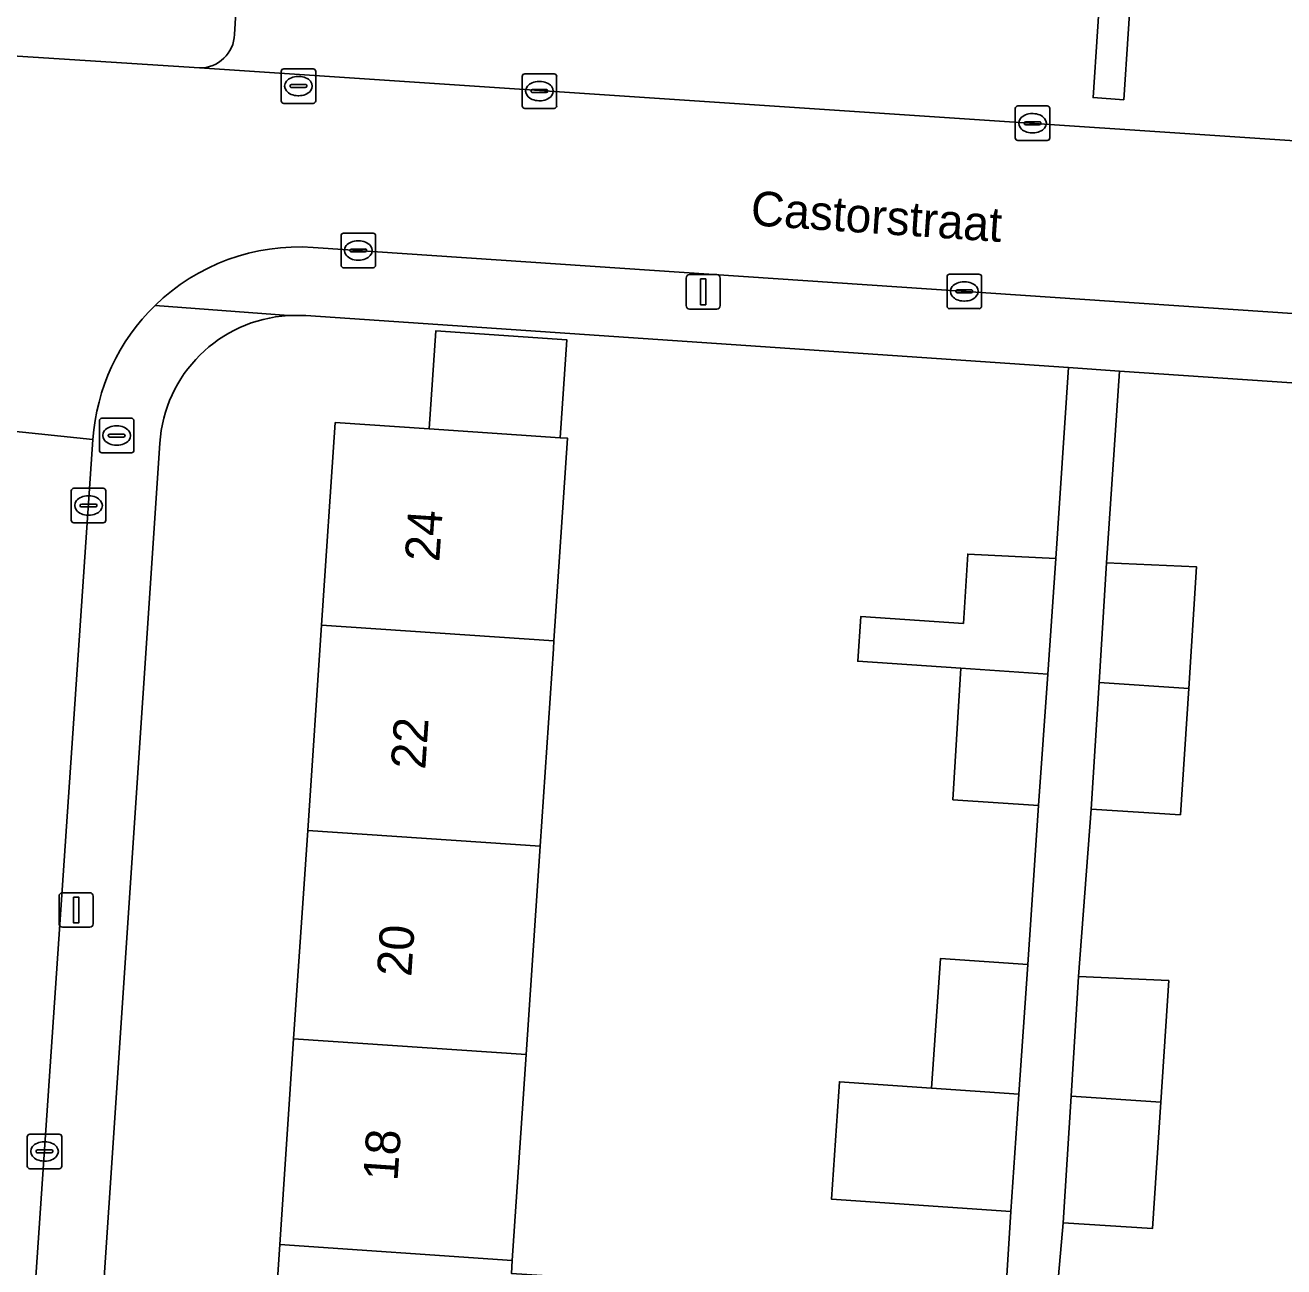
# Model space of a CAD drawing. Extents: x 161848 to 162726, y 385382 to 386521.
# Drawn here: x 161942.63 to 161979.1, y 385678.71 to 385714.68 of the extents above; entities that cross this region are included whole.
import ezdxf

# ---------------------------------------------------------------- set-up
doc = ezdxf.new("R2010")
doc.units = 0
for name, color, linetype in [('IMGEO_Brandkraan', 7, 'Continuous'), ('IMGEO_Erf', 7, 'Continuous'), ('IMGEO_Kolk', 7, 'Continuous'), ('IMGEO_Lichtmast', 7, 'Continuous'), ('IMGEO_Openbare_ruimte_label', 7, 'Continuous'), ('IMGEO_Pand', 7, 'Continuous'), ('IMGEO_Pand_nummerreeks', 7, 'Continuous'), ('IMGEO_Parkeervlak_open', 7, 'Continuous'), ('IMGEO_Rijbaan_lokaal_open', 7, 'Continuous'), ('IMGEO_Rioolput', 7, 'Continuous'), ('IMGEO_Voetpad_open', 7, 'Continuous')]:
    doc.layers.add(name, color=color, linetype=linetype)

msp = doc.modelspace()

# ---------------------------------------------------------------- linework, layer by layer
at = {"layer": 'IMGEO_Brandkraan'}
for p, q in [((161944.851, 385703.289), (161945.703, 385703.289)), ((161944.776, 385702.363), (161944.776, 385703.215)), ((161945.264, 385703.069), (161945.289, 385703.069)), ((161945.777, 385703.215), (161945.777, 385702.363)), ((161945.035, 385702.783), (161945.035, 385702.795)), ((161945.473, 385702.746), (161945.075, 385702.746)), ((161945.078, 385702.832), (161945.476, 385702.832)), ((161945.287, 385702.509), (161945.262, 385702.509)), ((161945.519, 385702.795), (161945.519, 385702.783)), ((161945.703, 385702.289), (161944.851, 385702.289))]:
    msp.add_line(p, q, dxfattribs=at)
for points in [[(161944.851, 385703.289), (161945.703, 385703.289)], [(161944.776, 385702.363), (161944.776, 385703.215)], [(161945.777, 385703.215), (161945.777, 385702.363)], [(161945.703, 385702.289), (161944.851, 385702.289)]]:
    msp.add_lwpolyline(points, dxfattribs=at)
for centre, radius, start, end in [((161944.853, 385703.213), 0.0765, 91.552, 178.448), ((161944.853, 385703.213), 0.0765, 91.552, 178.448), ((161945.701, 385703.213), 0.0765, 1.552, 88.448), ((161945.701, 385703.213), 0.0765, 1.552, 88.448), ((161945.075, 385702.792), 0.0403, 85.8775, 175.7526), ((161945.072, 385702.782), 0.0366, 178.938, 274.7102), ((161945.476, 385702.789), 0.043, 264.8664, 352.4533), ((161945.48, 385702.794), 0.0386, 1.7309, 96.639), ((161944.853, 385702.365), 0.0765, 181.552, 268.448), ((161944.853, 385702.365), 0.0765, 181.552, 268.448), ((161945.701, 385702.365), 0.0765, 271.552, 358.448), ((161945.701, 385702.365), 0.0765, 271.552, 358.448)]:
    msp.add_arc(centre, radius, start, end, dxfattribs=at)
for centre, major_axis, ratio, start_param, end_param in [((161945.263, 385702.789), (-0.387, 0.002), 0.722429, 4.712389, 7.853982), ((161945.288, 385702.789), (-0.39, 0.002), 0.717154, 1.570796, 4.712389)]:
    msp.add_ellipse(centre, major_axis=major_axis, ratio=ratio, start_param=start_param, end_param=end_param, dxfattribs=at)
at = {"layer": 'IMGEO_Erf'}
for points in [[(161970.385, 385668.193), (161967.899, 385668.362), (161968.129, 385672.173), (161968.329, 385675.481), (161970.879, 385675.348), (161971.188, 385680.308), (161965.988, 385680.667), (161966.222, 385684.067), (161968.889, 385683.883), (161969.148, 385687.638), (161971.682, 385687.463), (161971.995, 385692.068), (161969.509, 385692.237), (161969.739, 385696.048), (161966.755, 385696.251), (161966.843, 385697.548), (161969.817, 385697.346), (161969.939, 385699.356), (161972.489, 385699.223), (161972.865, 385704.758), (161950.757, 385706.262)], [(161949.605, 385673.424), (161950.004, 385679.348), (161950.406, 385685.311), (161950.813, 385691.345), (161951.215, 385697.299), (161951.61, 385703.166), (161954.33, 385702.982), (161954.523, 385705.821), (161958.321, 385705.564), (161958.128, 385702.725), (161958.345, 385702.71), (161957.95, 385696.844), (161957.934, 385696.609), (161957.548, 385690.89), (161957.142, 385684.856), (161956.74, 385678.892), (161956.715, 385678.515)], [(162001.131, 385702.827), (161999.588, 385702.941), (161974.338, 385704.658), (161973.96, 385699.104), (161976.574, 385698.983), (161976.344, 385695.463), (161976.105, 385691.802), (161973.517, 385691.96), (161973.151, 385687.121), (161975.765, 385687), (161975.535, 385683.48), (161975.296, 385679.819), (161972.708, 385679.977), (161972.485, 385677.457)], [(161946.526, 385702.567), (161941.6, 385628.889)]]:
    msp.add_lwpolyline(points, dxfattribs=at)
for centre, radius, start, end in [((161950.488, 385702.3), 3.971, 93.3925, 176.1445), ((161950.489, 385702.298), 3.973, 86.1361, 93.4092)]:
    msp.add_arc(centre, radius, start, end, dxfattribs=at)
at = {"layer": 'IMGEO_Kolk'}
for p, q in [((161957.027, 385712.342), (161957.027, 385713.194)), ((161957.102, 385713.268), (161957.954, 385713.268)), ((161958.028, 385713.194), (161958.028, 385712.342)), ((161957.286, 385712.762), (161957.286, 385712.774)), ((161957.724, 385712.725), (161957.326, 385712.725)), ((161957.329, 385712.811), (161957.727, 385712.811)), ((161957.515, 385713.048), (161957.54, 385713.048)), ((161957.77, 385712.774), (161957.77, 385712.762)), ((161957.538, 385712.488), (161957.513, 385712.488)), ((161957.954, 385712.268), (161957.102, 385712.268)), ((161971.319, 385711.411), (161971.319, 385712.263)), ((161971.394, 385712.337), (161972.246, 385712.337)), ((161971.807, 385712.117), (161971.832, 385712.117)), ((161972.32, 385712.263), (161972.32, 385711.411)), ((161971.578, 385711.831), (161971.578, 385711.843)), ((161972.016, 385711.794), (161971.618, 385711.794)), ((161971.621, 385711.88), (161972.019, 385711.88)), ((161972.062, 385711.843), (161972.062, 385711.831)), ((161972.246, 385711.337), (161971.394, 385711.337)), ((161971.83, 385711.557), (161971.805, 385711.557)), ((161951.779, 385707.724), (161951.779, 385708.576)), ((161951.854, 385708.65), (161952.706, 385708.65)), ((161952.267, 385708.43), (161952.292, 385708.43)), ((161952.78, 385708.576), (161952.78, 385707.724)), ((161952.038, 385708.144), (161952.038, 385708.156)), ((161952.476, 385708.107), (161952.078, 385708.107)), ((161952.081, 385708.193), (161952.479, 385708.193)), ((161952.522, 385708.156), (161952.522, 385708.144)), ((161952.706, 385707.65), (161951.854, 385707.65)), ((161952.29, 385707.87), (161952.265, 385707.87)), ((161969.34, 385706.539), (161969.34, 385707.391)), ((161969.415, 385707.465), (161970.267, 385707.465)), ((161970.341, 385707.391), (161970.341, 385706.539)), ((161969.599, 385706.959), (161969.599, 385706.971)), ((161970.037, 385706.922), (161969.639, 385706.922)), ((161969.642, 385707.008), (161970.04, 385707.008)), ((161969.828, 385707.245), (161969.853, 385707.245)), ((161970.083, 385706.971), (161970.083, 385706.959)), ((161969.851, 385706.685), (161969.826, 385706.685)), ((161970.267, 385706.465), (161969.415, 385706.465)), ((161943.961, 385700.336), (161943.961, 385701.188)), ((161944.036, 385701.262), (161944.888, 385701.262)), ((161944.962, 385701.188), (161944.962, 385700.336)), ((161944.22, 385700.756), (161944.22, 385700.768)), ((161944.658, 385700.719), (161944.26, 385700.719)), ((161944.263, 385700.805), (161944.661, 385700.805)), ((161944.449, 385701.042), (161944.474, 385701.042)), ((161944.704, 385700.768), (161944.704, 385700.756)), ((161944.472, 385700.482), (161944.447, 385700.482)), ((161944.888, 385700.262), (161944.036, 385700.262)), ((161942.685, 385681.623), (161942.685, 385682.475)), ((161942.76, 385682.549), (161943.612, 385682.549)), ((161943.686, 385682.475), (161943.686, 385681.623)), ((161942.987, 385682.092), (161943.385, 385682.092)), ((161943.173, 385682.329), (161943.198, 385682.329)), ((161942.944, 385682.043), (161942.944, 385682.055)), ((161943.382, 385682.006), (161942.984, 385682.006)), ((161943.196, 385681.769), (161943.171, 385681.769)), ((161943.428, 385682.055), (161943.428, 385682.043)), ((161943.612, 385681.549), (161942.76, 385681.549))]:
    msp.add_line(p, q, dxfattribs=at)
for points in [[(161957.027, 385712.342), (161957.027, 385713.194)], [(161957.102, 385713.268), (161957.954, 385713.268)], [(161958.028, 385713.194), (161958.028, 385712.342)], [(161957.954, 385712.268), (161957.102, 385712.268)], [(161971.319, 385711.411), (161971.319, 385712.263)], [(161971.394, 385712.337), (161972.246, 385712.337)], [(161972.32, 385712.263), (161972.32, 385711.411)], [(161972.246, 385711.337), (161971.394, 385711.337)], [(161951.779, 385707.724), (161951.779, 385708.576)], [(161951.854, 385708.65), (161952.706, 385708.65)], [(161952.78, 385708.576), (161952.78, 385707.724)], [(161952.706, 385707.65), (161951.854, 385707.65)], [(161969.34, 385706.539), (161969.34, 385707.391)], [(161969.415, 385707.465), (161970.267, 385707.465)], [(161970.341, 385707.391), (161970.341, 385706.539)], [(161970.267, 385706.465), (161969.415, 385706.465)], [(161943.961, 385700.336), (161943.961, 385701.188)], [(161944.036, 385701.262), (161944.888, 385701.262)], [(161944.962, 385701.188), (161944.962, 385700.336)], [(161944.888, 385700.262), (161944.036, 385700.262)], [(161942.685, 385681.623), (161942.685, 385682.475)], [(161942.76, 385682.549), (161943.612, 385682.549)], [(161943.686, 385682.475), (161943.686, 385681.623)], [(161943.612, 385681.549), (161942.76, 385681.549)]]:
    msp.add_lwpolyline(points, dxfattribs=at)
for centre, radius, start, end in [((161957.104, 385713.192), 0.0765, 91.552, 178.448), ((161957.104, 385713.192), 0.0765, 91.552, 178.448), ((161957.952, 385713.192), 0.0765, 1.552, 88.448), ((161957.952, 385713.192), 0.0765, 1.552, 88.448), ((161957.326, 385712.771), 0.0403, 85.8775, 175.7526), ((161957.323, 385712.761), 0.0366, 178.938, 274.7102), ((161957.727, 385712.768), 0.043, 264.8664, 352.4533), ((161957.731, 385712.773), 0.0386, 1.7309, 96.639), ((161957.104, 385712.344), 0.0765, 181.552, 268.448), ((161957.104, 385712.344), 0.0765, 181.552, 268.448), ((161957.952, 385712.344), 0.0765, 271.552, 358.448), ((161957.952, 385712.344), 0.0765, 271.552, 358.448), ((161971.396, 385712.261), 0.0765, 91.552, 178.448), ((161971.396, 385712.261), 0.0765, 91.552, 178.448), ((161972.244, 385712.261), 0.0765, 1.552, 88.448), ((161972.244, 385712.261), 0.0765, 1.552, 88.448), ((161971.618, 385711.84), 0.0403, 85.8775, 175.7526), ((161971.615, 385711.83), 0.0366, 178.938, 274.7102), ((161972.019, 385711.837), 0.043, 264.8664, 352.4533), ((161972.023, 385711.842), 0.0386, 1.7309, 96.639), ((161971.396, 385711.413), 0.0765, 181.552, 268.448), ((161971.396, 385711.413), 0.0765, 181.552, 268.448), ((161972.244, 385711.413), 0.0765, 271.552, 358.448), ((161972.244, 385711.413), 0.0765, 271.552, 358.448), ((161951.856, 385708.574), 0.0765, 91.552, 178.448), ((161951.856, 385708.574), 0.0765, 91.552, 178.448), ((161952.704, 385708.574), 0.0765, 1.552, 88.448), ((161952.704, 385708.574), 0.0765, 1.552, 88.448), ((161952.078, 385708.153), 0.0403, 85.8775, 175.7526), ((161952.075, 385708.143), 0.0366, 178.938, 274.7102), ((161952.479, 385708.15), 0.043, 264.8664, 352.4533), ((161952.483, 385708.155), 0.0386, 1.7309, 96.639), ((161951.856, 385707.726), 0.0765, 181.552, 268.448), ((161951.856, 385707.726), 0.0765, 181.552, 268.448), ((161952.704, 385707.726), 0.0765, 271.552, 358.448), ((161952.704, 385707.726), 0.0765, 271.552, 358.448), ((161969.417, 385707.389), 0.0765, 91.552, 178.448), ((161969.417, 385707.389), 0.0765, 91.552, 178.448), ((161970.265, 385707.389), 0.0765, 1.552, 88.448), ((161970.265, 385707.389), 0.0765, 1.552, 88.448), ((161969.639, 385706.968), 0.0403, 85.8775, 175.7526), ((161969.636, 385706.958), 0.0366, 178.938, 274.7102), ((161970.04, 385706.965), 0.043, 264.8664, 352.4533), ((161970.044, 385706.97), 0.0386, 1.7309, 96.639), ((161969.417, 385706.541), 0.0765, 181.552, 268.448), ((161969.417, 385706.541), 0.0765, 181.552, 268.448), ((161970.265, 385706.541), 0.0765, 271.552, 358.448), ((161970.265, 385706.541), 0.0765, 271.552, 358.448), ((161944.038, 385701.186), 0.0765, 91.552, 178.448), ((161944.038, 385701.186), 0.0765, 91.552, 178.448), ((161944.886, 385701.186), 0.0765, 1.552, 88.448), ((161944.886, 385701.186), 0.0765, 1.552, 88.448), ((161944.26, 385700.765), 0.0403, 85.8775, 175.7526), ((161944.257, 385700.755), 0.0366, 178.938, 274.7102), ((161944.661, 385700.762), 0.043, 264.8664, 352.4533), ((161944.665, 385700.767), 0.0386, 1.7309, 96.639), ((161944.038, 385700.338), 0.0765, 181.552, 268.448), ((161944.038, 385700.338), 0.0765, 181.552, 268.448), ((161944.886, 385700.338), 0.0765, 271.552, 358.448), ((161944.886, 385700.338), 0.0765, 271.552, 358.448), ((161942.762, 385682.473), 0.0765, 91.552, 178.448), ((161942.762, 385682.473), 0.0765, 91.552, 178.448), ((161943.61, 385682.473), 0.0765, 1.552, 88.448), ((161943.61, 385682.473), 0.0765, 1.552, 88.448), ((161942.984, 385682.052), 0.0403, 85.8775, 175.7526), ((161943.389, 385682.054), 0.0386, 1.7309, 96.639), ((161942.981, 385682.042), 0.0366, 178.938, 274.7102), ((161943.385, 385682.049), 0.043, 264.8664, 352.4533), ((161942.762, 385681.625), 0.0765, 181.552, 268.448), ((161942.762, 385681.625), 0.0765, 181.552, 268.448), ((161943.61, 385681.625), 0.0765, 271.552, 358.448), ((161943.61, 385681.625), 0.0765, 271.552, 358.448)]:
    msp.add_arc(centre, radius, start, end, dxfattribs=at)
for centre, major_axis, ratio, start_param, end_param in [((161957.514, 385712.768), (-0.387, 0.002), 0.722429, 4.712389, 7.853982), ((161957.539, 385712.768), (-0.39, 0.002), 0.717154, 1.570796, 4.712389), ((161971.806, 385711.837), (-0.387, 0.002), 0.722429, 4.712389, 7.853982), ((161971.831, 385711.837), (-0.39, 0.002), 0.717154, 1.570796, 4.712389), ((161952.266, 385708.15), (-0.387, 0.002), 0.722429, 4.712389, 7.853982), ((161952.291, 385708.15), (-0.39, 0.002), 0.717154, 1.570796, 4.712389), ((161969.827, 385706.965), (-0.387, 0.002), 0.722429, 4.712389, 7.853982), ((161969.852, 385706.965), (-0.39, 0.002), 0.717154, 1.570796, 4.712389), ((161944.448, 385700.762), (-0.387, 0.002), 0.722429, 4.712389, 7.853982), ((161944.473, 385700.762), (-0.39, 0.002), 0.717154, 1.570796, 4.712389), ((161943.172, 385682.049), (-0.387, 0.002), 0.722429, 4.712389, 7.853982), ((161943.197, 385682.049), (-0.39, 0.002), 0.717154, 1.570796, 4.712389)]:
    msp.add_ellipse(centre, major_axis=major_axis, ratio=ratio, start_param=start_param, end_param=end_param, dxfattribs=at)
at = {"layer": 'IMGEO_Lichtmast'}
for p, q in [((161961.778, 385706.552), (161961.778, 385707.352)), ((161961.778, 385707.352), (161961.778, 385706.552)), ((161961.878, 385707.452), (161962.668, 385707.452)), ((161962.668, 385707.452), (161961.878, 385707.452)), ((161962.768, 385707.352), (161962.768, 385706.552)), ((161962.768, 385706.552), (161962.768, 385707.352)), ((161962.668, 385706.452), (161961.878, 385706.452)), ((161961.878, 385706.452), (161962.668, 385706.452)), ((161943.607, 385688.645), (161943.607, 385689.445)), ((161943.607, 385689.445), (161943.607, 385688.645)), ((161943.707, 385689.545), (161944.497, 385689.545)), ((161944.497, 385689.545), (161943.707, 385689.545)), ((161944.597, 385689.445), (161944.597, 385688.645)), ((161944.597, 385688.645), (161944.597, 385689.445)), ((161944.497, 385688.545), (161943.707, 385688.545)), ((161943.707, 385688.545), (161944.497, 385688.545))]:
    msp.add_line(p, q, dxfattribs=at)
for points in [[(161962.198, 385707.327), (161962.348, 385707.327), (161962.348, 385706.577), (161962.198, 385706.577), (161962.198, 385707.327)], [(161944.027, 385689.42), (161944.177, 385689.42), (161944.177, 385688.67), (161944.027, 385688.67), (161944.027, 385689.42)]]:
    msp.add_lwpolyline(points, dxfattribs=at)
for centre, start, end in [((161961.878, 385707.352), 90, 180), ((161961.878, 385707.352), 90, 180), ((161962.668, 385707.352), 0, 90), ((161962.668, 385707.352), 360, 90), ((161961.878, 385706.552), 180, 270), ((161961.878, 385706.552), 180, 270), ((161962.668, 385706.552), 270, 0), ((161962.668, 385706.552), 270, 0), ((161943.707, 385689.445), 90, 180), ((161943.707, 385689.445), 90, 180), ((161944.497, 385689.445), 0, 90), ((161944.497, 385689.445), 360, 90), ((161943.707, 385688.645), 180, 270), ((161943.707, 385688.645), 180, 270), ((161944.497, 385688.645), 270, 0), ((161944.497, 385688.645), 270, 0)]:
    msp.add_arc(centre, 0.1, start, end, dxfattribs=at)
at = {"layer": 'IMGEO_Pand'}
for points in [[(161954.33, 385702.982), (161958.128, 385702.725), (161958.321, 385705.564), (161954.523, 385705.821)], [(161958.345, 385702.71), (161958.128, 385702.725), (161954.33, 385702.982), (161951.61, 385703.166), (161951.215, 385697.299), (161957.95, 385696.844)], [(161972.489, 385699.223), (161969.939, 385699.356), (161969.817, 385697.346), (161966.843, 385697.548), (161966.755, 385696.251), (161969.739, 385696.048), (161972.258, 385695.877)], [(161976.344, 385695.463), (161976.574, 385698.983), (161973.96, 385699.104), (161973.745, 385695.637)], [(161957.95, 385696.844), (161951.215, 385697.299), (161950.813, 385691.345), (161957.548, 385690.89), (161957.934, 385696.609)], [(161969.739, 385696.048), (161969.509, 385692.237), (161971.995, 385692.068), (161972.258, 385695.877)], [(161973.745, 385695.637), (161973.517, 385691.96), (161976.105, 385691.802), (161976.344, 385695.463)], [(161957.548, 385690.89), (161950.813, 385691.345), (161950.406, 385685.311), (161957.142, 385684.856)], [(161971.423, 385683.712), (161971.682, 385687.463), (161969.148, 385687.638), (161968.889, 385683.883)], [(161975.765, 385687), (161973.151, 385687.121), (161972.936, 385683.654), (161975.535, 385683.48)], [(161957.142, 385684.856), (161950.406, 385685.311), (161950.004, 385679.348), (161956.74, 385678.892)], [(161968.889, 385683.883), (161966.222, 385684.067), (161965.988, 385680.667), (161971.188, 385680.308), (161971.423, 385683.712)], [(161972.708, 385679.977), (161975.296, 385679.819), (161975.535, 385683.48), (161972.936, 385683.654)], [(161959.675, 385678.316), (161956.715, 385678.515), (161956.74, 385678.892), (161950.004, 385679.348), (161949.605, 385673.424), (161956.34, 385672.969), (161956.328, 385672.786), (161959.289, 385672.587)]]:
    msp.add_lwpolyline(points, close=True, dxfattribs=at)
at = {"layer": 'IMGEO_Parkeervlak_open'}
for points in [[(162002.637, 385710.748), (162002.853, 385714.41), (162002.123, 385714.419), (162000, 385714.682), (161974.711, 385716.344), (161974.461, 385712.518), (161973.573, 385712.578), (161973.823, 385716.419), (161948.917, 385718.068), (161948.696, 385714.412)], [(161947.673, 385713.437), (162000, 385709.96), (162003.231, 385709.718), (162002.926, 385709.929)]]:
    msp.add_lwpolyline(points, dxfattribs=at)
msp.add_arc((161947.677, 385714.457), 1.02, 269.7854, 357.4622, dxfattribs=at)
at = {"layer": 'IMGEO_Rijbaan_lokaal_open'}
for points in [[(161947.673, 385713.437), (161940.291, 385713.919), (161939.917, 385708.382), (161939.569, 385703.191), (161944.591, 385702.676)], [(161950.969, 385708.24), (162000, 385704.93), (162001.843, 385704.706), (162002.905, 385704.639), (162003.231, 385709.718), (162000, 385709.96), (161947.673, 385713.437)]]:
    msp.add_lwpolyline(points, dxfattribs=at)
msp.add_lwpolyline([(161942.144, 385666.78), (161944.591, 385702.676), (161939.569, 385703.191), (161935.985, 385649.661), (161934.481, 385627.029), (161934.124, 385621.658), (161939.176, 385621.222)], close=True, dxfattribs=at)
for centre, radius, start, end in [((161950.568, 385702.259), 5.995, 86.1604, 134.1651), ((161950.561, 385702.267), 5.984, 134.1754, 176.0836)]:
    msp.add_arc(centre, radius, start, end, dxfattribs=at)
at = {"layer": 'IMGEO_Rioolput'}
for p, q in [((161950.045, 385712.487), (161950.045, 385713.339)), ((161950.12, 385713.413), (161950.972, 385713.413)), ((161950.533, 385713.193), (161950.558, 385713.193)), ((161951.046, 385713.339), (161951.046, 385712.487)), ((161950.304, 385712.907), (161950.304, 385712.919)), ((161950.742, 385712.87), (161950.344, 385712.87)), ((161950.347, 385712.956), (161950.745, 385712.956)), ((161950.788, 385712.919), (161950.788, 385712.907)), ((161950.972, 385712.413), (161950.12, 385712.413)), ((161950.556, 385712.633), (161950.531, 385712.633))]:
    msp.add_line(p, q, dxfattribs=at)
for points in [[(161950.045, 385712.487), (161950.045, 385713.339)], [(161950.12, 385713.413), (161950.972, 385713.413)], [(161951.046, 385713.339), (161951.046, 385712.487)], [(161950.972, 385712.413), (161950.12, 385712.413)]]:
    msp.add_lwpolyline(points, dxfattribs=at)
for centre, radius, start, end in [((161950.122, 385713.337), 0.0765, 91.552, 178.448), ((161950.122, 385713.337), 0.0765, 91.552, 178.448), ((161950.97, 385713.337), 0.0765, 1.552, 88.448), ((161950.97, 385713.337), 0.0765, 1.552, 88.448), ((161950.344, 385712.916), 0.0403, 85.8775, 175.7526), ((161950.341, 385712.906), 0.0366, 178.938, 274.7102), ((161950.745, 385712.913), 0.043, 264.8664, 352.4533), ((161950.749, 385712.918), 0.0386, 1.7309, 96.639), ((161950.122, 385712.489), 0.0765, 181.552, 268.448), ((161950.122, 385712.489), 0.0765, 181.552, 268.448), ((161950.97, 385712.489), 0.0765, 271.552, 358.448), ((161950.97, 385712.489), 0.0765, 271.552, 358.448)]:
    msp.add_arc(centre, radius, start, end, dxfattribs=at)
for centre, major_axis, ratio, start_param, end_param in [((161950.532, 385712.913), (-0.387, 0.002), 0.722429, 4.712389, 7.853982), ((161950.557, 385712.913), (-0.39, 0.002), 0.717154, 1.570796, 4.712389)]:
    msp.add_ellipse(centre, major_axis=major_axis, ratio=ratio, start_param=start_param, end_param=end_param, dxfattribs=at)
at = {"layer": 'IMGEO_Voetpad_open'}
for points in [[(161948.696, 385714.412), (161948.917, 385718.068), (161973.823, 385716.419), (161973.573, 385712.578), (161974.461, 385712.518), (161974.711, 385716.344), (162000, 385714.682), (162002.123, 385714.419), (162002.853, 385714.41), (162004.404, 385714.393), (162004.634, 385716.496), (162003.988, 385716.55), (162004.055, 385717.404), (162000, 385717.677), (161952.414, 385720.877), (161952.368, 385719.986), (161951.733, 385720.035), (161943.842, 385720.56), (161933.55, 385721.254), (161933.437, 385721.262), (161933.361, 385721.455), (161931.759, 385723.691), (161930.762, 385726.378), (161930.57, 385729.261)], [(161937.895, 385714.111), (161939.793, 385713.952), (161940.291, 385713.919), (161947.673, 385713.437)], [(162003.492, 385700.232), (162003.78, 385704.564), (162002.905, 385704.639), (162001.843, 385704.706), (162000, 385704.93), (161950.969, 385708.24)], [(161950.253, 385706.264), (161946.391, 385706.559)], [(161946.391, 385706.559), (161950.253, 385706.264)], [(161950.757, 385706.262), (161972.865, 385704.758), (161974.338, 385704.658), (161999.588, 385702.941), (162001.131, 385702.827)], [(161972.485, 385677.457), (161972.708, 385679.977), (161972.936, 385683.654), (161973.151, 385687.121), (161973.517, 385691.96), (161973.745, 385695.637), (161973.96, 385699.104), (161974.338, 385704.658), (161972.865, 385704.758), (161972.489, 385699.223), (161972.258, 385695.877), (161971.995, 385692.068), (161971.682, 385687.463), (161971.423, 385683.712), (161971.188, 385680.308), (161970.879, 385675.348)], [(161944.591, 385702.676), (161942.144, 385666.78), (161939.176, 385621.222)], [(161941.087, 385621.217), (161941.573, 385628.49), (161941.6, 385628.889), (161946.526, 385702.567)]]:
    msp.add_lwpolyline(points, dxfattribs=at)
for centre, radius, start, end in [((161947.677, 385714.457), 1.02, 269.7854, 357.4622), ((161950.568, 385702.259), 5.995, 86.1604, 134.1651), ((161950.561, 385702.267), 5.984, 134.1754, 176.0836), ((161950.488, 385702.3), 3.971, 93.3925, 176.1445), ((161950.489, 385702.298), 3.973, 86.1361, 93.4092)]:
    msp.add_arc(centre, radius, start, end, dxfattribs=at)

# ---------------------------------------------------------------- texts
at = {"layer": 'IMGEO_Openbare_ruimte_label'}
msp.add_text('Castorstraat', height=1, rotation=356.1593, dxfattribs=at).set_placement((161963.632, 385708.884))
at = {"layer": 'IMGEO_Pand_nummerreeks'}
for s, rotation, p in [('24', 86.1442, (161954.625, 385699.115)), ('22', 86.1442, (161954.219, 385693.1)), ('20', 86.1435, (161953.814, 385687.095)), ('18', 86.1435, (161953.415, 385681.174))]:
    msp.add_text(s, height=1, rotation=rotation, dxfattribs=at).set_placement(p)

doc.saveas('drawing.dxf')
